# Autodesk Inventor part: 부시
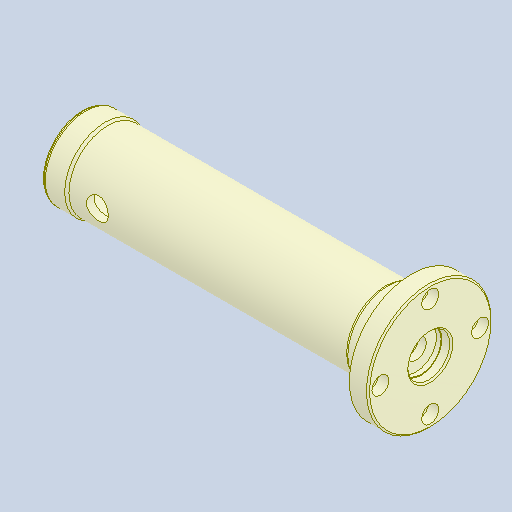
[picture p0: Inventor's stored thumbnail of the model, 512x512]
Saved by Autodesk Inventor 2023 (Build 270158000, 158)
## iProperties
Created: 2024-07
Part Number: 부시
Material: 강철, 탄소
Document SubType Name: Modeling
Designer: home
Density: 7.85 g/cm^3
Appearance: 기본값
Author: jhkim
Sending System: Autodesk Inventor 2025
Preprocessor: ST-DEVELOPER v20
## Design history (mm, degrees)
feature "솔리드1"
node "솔리드2"
